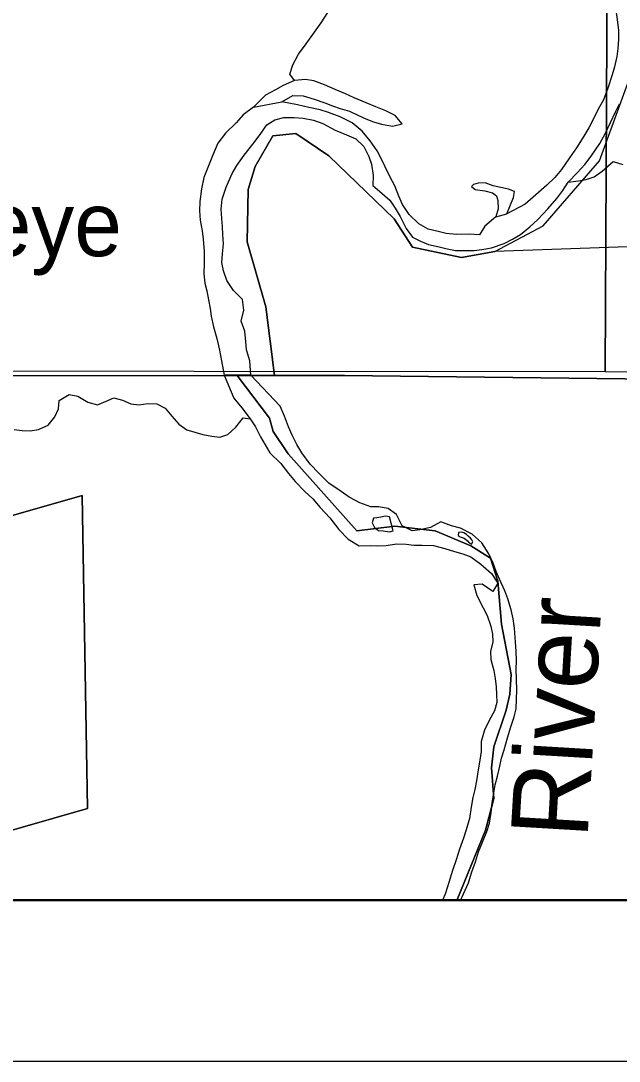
# Model space of a CAD drawing. Extents: x 0 to 680, y 0 to 440.
# Drawn here: x 388.24 to 401.22, y 173.86 to 196.42 of the extents above; entities that cross this region are included whole.
import ezdxf

# ---------------------------------------------------------------- set-up
doc = ezdxf.new("R2010")
doc.units = 0
for name, color, linetype in [('GM_X_Adjacent_County', 7, 'Continuous'), ('GM_X_Corporation', 7, 'Continuous'), ('GM_X_County', 7, 'Continuous'), ('GM_X_Major_River', 7, 'Continuous'), ('GM_X_Major_River_Text', 7, 'Continuous'), ('GM_X_Minor_River', 7, 'Continuous'), ('GM_X_Section', 7, 'Continuous'), ('GM_X_Township', 7, 'Continuous'), ('GM_X_Unincorporated_Text', 7, 'Continuous'), ('SH_Data', 7, 'Continuous'), ('SH_Text', 7, 'Continuous')]:
    doc.layers.add(name, color=color, linetype=linetype)

msp = doc.modelspace()

# ---------------------------------------------------------------- linework, layer by layer
at = {"layer": 'GM_X_Adjacent_County'}
for points in [[(345.039, 415.359), (345.039, 188.757), (345.473, 188.756), (347.217, 188.747), (347.794, 188.745), (350.054, 188.756), (350.975, 188.76), (352.892, 188.767), (353.65, 188.774), (356.075, 188.765), (356.617, 188.773), (363.409, 188.772), (363.555, 188.769), (365.255, 188.724), (373.709, 188.721), (379.321, 188.719), (384.35, 188.722), (392.938, 188.728), (395.267, 188.729), (408.033, 188.58)], [(408.033, 188.58), (395.267, 188.729), (392.938, 188.728), (384.35, 188.722), (379.321, 188.719), (373.709, 188.721), (365.255, 188.724), (363.555, 188.769), (363.409, 188.772), (356.617, 188.773), (356.075, 188.765), (353.65, 188.774), (352.892, 188.767), (350.975, 188.76), (350.054, 188.756), (347.794, 188.745), (347.217, 188.747), (345.473, 188.756), (345.039, 188.757), (345.039, 177.346), (520.893, 177.346)]]:
    msp.add_lwpolyline(points, dxfattribs=at)
at = {"layer": 'GM_X_Corporation'}
for points in [[(387.677, 177.346), (397.702, 177.346), (398.321, 178.866), (398.507, 179.557), (398.454, 180.222), (398.507, 180.675), (398.773, 181.472), (398.853, 181.818), (398.88, 182.244), (398.667, 183.334), (398.587, 184.266), (398.428, 184.771), (398.002, 185.037), (397.231, 185.357), (396.353, 185.463), (395.529, 185.357), (394.04, 187.033), (393.721, 187.512), (393.641, 187.805), (392.94, 188.728), (393.745, 188.728), (393.562, 190.219), (393.157, 191.631), (393.177, 192.766), (393.328, 193.261), (393.712, 193.925), (394.21, 193.978), (394.924, 193.496), (396.34, 192.128), (396.739, 191.515), (397.803, 191.289), (398.528, 191.42), (399.57, 191.974), (400.796, 193.385), (401.458, 195.204)], [(387.677, 177.346), (397.702, 177.346), (398.321, 178.866), (398.507, 179.557), (398.454, 180.222), (398.507, 180.675), (398.773, 181.472), (398.853, 181.818), (398.88, 182.244), (398.667, 183.334), (398.587, 184.266), (398.428, 184.771), (398.002, 185.037), (397.231, 185.357), (396.353, 185.463), (395.529, 185.357), (394.04, 187.033), (393.721, 187.512), (393.641, 187.805), (392.94, 188.728), (393.745, 188.728), (393.562, 190.219), (393.157, 191.631), (393.177, 192.766), (393.328, 193.261), (393.712, 193.925), (394.21, 193.978), (394.924, 193.496), (396.34, 192.128), (396.739, 191.515), (397.803, 191.289), (398.528, 191.42), (399.57, 191.974), (400.796, 193.385), (401.458, 195.204)], [(403.05, 191.578), (398.528, 191.42), (397.803, 191.289), (396.739, 191.515), (396.34, 192.128), (394.924, 193.496), (394.21, 193.978), (393.712, 193.925), (393.328, 193.261), (393.177, 192.766), (393.157, 191.631), (393.562, 190.219), (393.745, 188.728), (392.94, 188.728), (393.641, 187.805), (393.721, 187.512), (394.04, 187.033), (395.529, 185.357), (396.353, 185.463), (397.231, 185.357), (398.002, 185.037), (398.428, 184.771), (398.587, 184.266), (398.667, 183.334), (398.88, 182.244), (398.853, 181.818), (398.773, 181.472), (398.507, 180.675), (398.454, 180.222), (398.507, 179.557), (398.321, 178.866), (397.702, 177.346), (409.232, 177.346)], [(403.05, 191.578), (398.528, 191.42), (397.803, 191.289), (396.739, 191.515), (396.34, 192.128), (394.924, 193.496), (394.21, 193.978), (393.712, 193.925), (393.328, 193.261), (393.177, 192.766), (393.157, 191.631), (393.562, 190.219), (393.745, 188.728), (392.94, 188.728), (393.641, 187.805), (393.721, 187.512), (394.04, 187.033), (395.529, 185.357), (396.353, 185.463), (397.231, 185.357), (398.002, 185.037), (398.428, 184.771), (398.587, 184.266), (398.667, 183.334), (398.88, 182.244), (398.853, 181.818), (398.773, 181.472), (398.507, 180.675), (398.454, 180.222), (398.507, 179.557), (398.321, 178.866), (397.702, 177.346), (409.232, 177.346)], [(385.376, 184.927), (389.574, 186.13), (389.692, 179.338), (387.542, 178.722)], [(385.376, 184.927), (389.574, 186.13), (389.692, 179.338), (387.542, 178.722)]]:
    msp.add_lwpolyline(points, dxfattribs=at)
msp.add_lwpolyline([(372.374, 177.346), (387.677, 177.346), (387.542, 178.722), (389.692, 179.338), (389.574, 186.13), (385.376, 184.927), (385.199, 185.413), (382.81, 184.4), (376.636, 184.293), (376.715, 179.713), (372.374, 180.017)], close=True, dxfattribs=at)
msp.add_lwpolyline([(372.374, 177.346), (387.677, 177.346), (387.542, 178.722), (389.692, 179.338), (389.574, 186.13), (385.376, 184.927), (385.199, 185.413), (382.81, 184.4), (376.636, 184.293), (376.715, 179.713), (372.374, 180.017)], close=True, dxfattribs=at)
at = {"layer": 'GM_X_County'}
for points in [[(345.039, 415.359), (345.039, 188.757), (345.473, 188.756), (347.217, 188.747), (347.794, 188.745), (350.054, 188.756), (350.975, 188.76), (352.892, 188.767), (353.65, 188.774), (356.075, 188.765), (356.617, 188.773), (363.409, 188.772), (363.555, 188.769), (365.255, 188.724), (373.709, 188.721), (379.321, 188.719), (384.35, 188.722), (392.938, 188.728), (395.267, 188.729), (408.033, 188.58)], [(408.033, 188.58), (395.267, 188.729), (392.938, 188.728), (384.35, 188.722), (379.321, 188.719), (373.709, 188.721), (365.255, 188.724), (363.555, 188.769), (363.409, 188.772), (356.617, 188.773), (356.075, 188.765), (353.65, 188.774), (352.892, 188.767), (350.975, 188.76), (350.054, 188.756), (347.794, 188.745), (347.217, 188.747), (345.473, 188.756), (345.039, 188.757), (345.039, 177.346), (520.893, 177.346)]]:
    msp.add_lwpolyline(points, dxfattribs=at)
at = {"layer": 'GM_X_Major_River'}
for p, q in [((393.293, 194.547), (393.908, 194.665)), ((398.548, 192.167), (398.789, 192.238)), ((393.232, 188.734), (392.657, 188.734)), ((392.657, 188.734), (393.232, 188.734))]:
    msp.add_line(p, q, dxfattribs=at)
for points in [[(401.149, 196.658), (401.186, 196.389), (401.21, 196.214), (401.207, 196.013), (401.191, 195.819), (401.168, 195.645), (401.118, 195.424), (401.068, 195.25), (400.977, 194.957), (400.88, 194.71), (400.769, 194.503), (400.679, 194.323), (400.562, 194.097), (400.452, 193.917), (400.294, 193.665), (400.143, 193.446), (399.972, 193.193), (399.828, 193.021), (399.652, 192.856), (399.414, 192.644), (399.183, 192.446), (398.789, 192.238)], [(393.908, 194.665), (394.142, 194.804), (394.37, 194.794), (394.604, 194.723), (394.838, 194.64), (395.005, 194.577), (395.172, 194.521), (395.372, 194.458), (395.552, 194.375), (395.726, 194.292), (395.892, 194.229), (396.066, 194.18), (396.307, 194.136), (396.516, 194.187), (396.364, 194.37), (396.158, 194.467), (395.944, 194.557), (395.731, 194.641), (395.477, 194.751), (395.284, 194.835), (395.064, 194.932), (394.83, 195.035), (394.596, 195.119), (394.416, 195.149), (394.18, 195.125), (393.937, 195.021), (393.768, 194.923), (393.552, 194.805), (393.293, 194.547)], [(393.293, 194.547), (393.069, 194.383), (392.912, 194.21), (392.687, 193.985), (392.517, 193.767), (392.399, 193.493), (392.301, 193.24), (392.217, 193.02), (392.16, 192.779), (392.129, 192.504), (392.12, 192.303), (392.137, 192.095), (392.174, 191.867), (392.198, 191.685), (392.221, 191.417), (392.218, 191.175), (392.214, 190.934), (392.238, 190.732), (392.276, 190.564), (392.314, 190.369), (392.351, 190.181), (392.376, 190.013), (392.426, 189.784), (392.496, 189.535), (392.553, 189.28), (392.597, 189.044), (392.657, 188.734)], [(393.232, 188.734), (393.214, 189.049), (393.137, 189.285), (393.126, 189.466), (393.103, 189.694), (393.025, 189.91), (393.082, 190.144), (393.052, 190.379), (392.86, 190.569), (392.709, 190.786), (392.638, 191.002), (392.607, 191.177), (392.616, 191.364), (392.64, 191.585), (392.629, 191.787), (392.618, 191.961), (392.601, 192.136), (392.59, 192.337), (392.613, 192.551), (392.698, 192.812), (392.829, 193.112), (392.932, 193.285), (393.09, 193.51), (393.275, 193.743), (393.432, 193.955), (393.583, 194.168), (393.752, 194.272), (393.947, 194.323), (394.176, 194.327), (394.37, 194.311), (394.591, 194.267), (394.798, 194.191), (395.064, 194.053), (395.305, 193.949), (395.511, 193.859), (395.683, 193.696), (395.794, 193.479), (395.852, 193.311), (395.883, 193.069), (395.879, 192.848), (396.078, 192.677), (396.251, 192.534), (396.362, 192.358), (396.474, 192.175), (396.604, 191.919), (396.743, 191.729), (396.916, 191.639), (397.089, 191.57), (397.317, 191.52), (397.491, 191.477), (397.671, 191.441), (397.846, 191.439), (398.074, 191.442), (398.242, 191.46), (398.451, 191.497), (398.727, 191.594), (398.91, 191.685), (399.079, 191.79), (399.283, 191.955), (399.46, 192.114), (399.678, 192.345), (399.869, 192.564), (399.999, 192.743), (400.116, 192.923), (400.32, 193.135), (400.477, 193.307), (400.614, 193.486), (400.805, 193.758), (400.923, 193.985), (401.034, 194.218), (401.144, 194.444), (401.227, 194.624)], [(398.548, 192.167), (398.31, 191.969), (398.193, 191.783), (397.965, 191.792), (397.697, 191.79), (397.469, 191.806), (397.295, 191.849), (397.081, 191.899), (396.874, 192.016), (396.669, 192.22), (396.525, 192.436), (396.44, 192.619), (396.356, 192.841), (396.258, 193.03), (396.147, 193.253), (396.069, 193.422), (395.971, 193.598), (395.82, 193.821), (395.648, 194.025), (395.429, 194.209), (395.169, 194.34), (394.915, 194.431), (394.735, 194.487), (394.488, 194.544), (394.247, 194.601), (393.908, 194.665)], [(398.789, 192.238), (398.93, 192.591), (398.952, 192.718), (398.818, 192.773), (398.49, 192.845), (398.317, 192.908), (398.162, 192.903), (398.061, 192.871), (398.02, 192.825), (398.1, 192.763), (398.307, 192.733), (398.475, 192.691), (398.561, 192.629), (398.593, 192.521), (398.597, 192.34), (398.548, 192.167)], [(392.657, 188.734), (392.867, 188.236), (393.037, 188.031), (393.22, 187.786), (393.331, 187.616), (393.441, 187.399), (393.544, 187.223), (393.648, 187.053), (393.885, 186.82), (394.049, 186.602), (394.193, 186.432), (394.403, 186.213), (394.575, 186.055), (394.739, 185.864), (394.949, 185.639), (395.145, 185.387), (395.342, 185.181), (395.581, 185.036), (395.823, 185.044), (395.991, 185.034), (396.165, 185.044), (396.394, 185.08), (396.602, 185.069), (396.77, 185.046), (396.951, 185.049), (397.193, 185.044), (397.44, 184.979), (397.653, 184.914), (397.833, 184.864), (398.007, 184.8), (398.225, 184.635), (398.456, 184.435), (398.593, 184.225), (398.481, 184.046), (398.25, 184.205), (398.068, 184.188), (398.137, 183.959), (398.273, 183.694), (398.357, 183.525), (398.439, 183.295), (398.476, 183.12), (398.479, 182.953), (398.428, 182.746), (398.438, 182.571), (398.5, 182.335), (398.53, 182.16), (398.554, 181.978), (398.564, 181.811), (398.567, 181.636), (398.516, 181.456), (398.404, 181.244), (398.3, 181.038), (398.227, 180.791), (398.23, 180.576), (398.199, 180.389), (398.161, 180.175), (398.13, 179.941), (398.092, 179.754), (398.048, 179.58), (398.011, 179.367), (397.979, 179.119), (397.907, 178.879), (397.842, 178.692), (397.757, 178.459), (397.685, 178.226), (397.607, 177.993), (397.528, 177.733), (397.456, 177.5), (397.387, 177.346)], [(397.782, 177.346), (397.845, 177.485), (397.957, 177.724), (398.029, 177.964), (398.107, 178.184), (398.172, 178.398), (398.257, 178.611), (398.349, 178.843), (398.406, 179.017), (398.445, 179.251), (398.469, 179.458), (398.493, 179.632), (398.531, 179.853), (398.581, 180.039), (398.633, 180.26), (398.67, 180.427), (398.727, 180.613), (398.8, 180.873), (398.872, 181.107), (398.943, 181.327), (398.987, 181.5), (398.998, 181.708), (399.002, 181.909), (398.993, 182.137), (398.991, 182.359), (398.995, 182.54), (398.985, 182.748), (398.976, 182.949), (398.949, 183.252), (398.926, 183.453), (398.883, 183.649), (398.807, 183.885), (398.744, 184.061), (398.628, 184.311), (398.551, 184.481), (398.487, 184.656), (398.397, 184.859), (398.241, 185.097), (398.03, 185.289), (397.777, 185.415), (397.584, 185.466), (397.351, 185.558), (397.133, 185.434), (396.897, 185.385), (396.729, 185.362), (396.516, 185.467), (396.394, 185.711), (396.215, 185.848), (396.001, 185.879), (395.833, 185.883), (395.6, 185.968), (395.368, 186.093), (395.189, 186.211), (394.924, 186.397), (394.707, 186.61), (394.523, 186.808), (394.34, 187.053), (394.229, 187.236), (394.126, 187.433), (394.049, 187.616), (393.96, 187.845), (393.87, 188.062), (393.232, 188.734)], [(396.32, 185.363), (396.238, 185.667), (396.151, 185.675), (396.05, 185.657), (395.963, 185.645), (395.895, 185.633), (395.867, 185.533), (395.918, 185.432)], [(395.918, 185.432), (396.004, 185.37), (396.105, 185.361), (396.238, 185.338), (396.32, 185.363)], [(397.809, 185.334), (397.735, 185.322), (397.727, 185.262), (397.774, 185.227), (397.86, 185.199)], [(397.86, 185.199), (397.887, 185.178), (397.933, 185.143), (397.966, 185.103), (398.019, 185.068), (398.047, 185.121), (398.027, 185.162), (397.995, 185.203), (397.949, 185.244), (397.909, 185.278), (397.856, 185.319), (397.809, 185.334)]]:
    msp.add_lwpolyline(points, dxfattribs=at)
at = {"layer": 'GM_X_Minor_River'}
for points in [[(394.18, 195.125), (394.082, 195.261), (394.145, 195.468), (394.269, 195.701), (394.433, 195.92), (394.612, 196.172), (394.755, 196.378), (394.9, 196.604)], [(400.116, 192.923), (400.338, 192.953), (400.506, 192.978), (400.681, 193.036), (400.851, 193.161), (401.095, 193.372), (401.302, 193.302)], [(388.102, 187.559), (388.276, 187.534), (388.45, 187.53), (388.626, 187.559), (388.836, 187.654), (388.982, 187.832), (389.06, 188.004), (389.078, 188.185), (389.296, 188.314), (389.483, 188.282), (389.695, 188.149), (389.908, 188.09), (390.078, 188.166), (390.261, 188.242), (390.448, 188.197), (390.627, 188.112), (390.814, 188.094), (390.996, 188.123), (391.191, 188.118), (391.376, 188.02), (391.52, 187.848), (391.67, 187.67), (391.848, 187.551), (392.194, 187.449), (392.388, 187.41), (392.562, 187.392), (392.731, 187.449), (392.91, 187.605), (393.069, 187.809), (393.22, 187.786)]]:
    msp.add_lwpolyline(points, dxfattribs=at)
at = {"layer": 'GM_X_Section'}
for points in [[(401.002, 206.368), (418.587, 206.469), (418.28, 188.572), (400.916, 188.809)], [(383.187, 206.393), (401.002, 206.368), (400.916, 188.809), (383.08, 188.821)]]:
    msp.add_lwpolyline(points, close=True, dxfattribs=at)
at = {"layer": 'GM_X_Township'}
for points in [[(345.039, 295.02), (345.039, 188.757), (345.473, 188.756), (347.217, 188.747), (347.794, 188.745), (350.054, 188.756), (350.975, 188.76), (352.892, 188.767), (353.65, 188.774), (356.075, 188.765), (356.617, 188.773), (363.409, 188.772), (363.555, 188.769), (365.255, 188.724), (373.709, 188.721), (379.321, 188.719), (384.35, 188.722), (392.938, 188.728), (395.267, 188.729), (408.033, 188.58), (418.103, 188.464), (418.29, 277.524)], [(408.033, 188.58), (395.267, 188.729), (392.938, 188.728), (393.641, 187.805), (393.721, 187.512), (394.04, 187.033), (395.529, 185.357), (396.353, 185.463), (397.231, 185.357), (398.002, 185.037), (398.428, 184.771), (398.587, 184.266), (398.667, 183.334), (398.88, 182.244), (398.853, 181.818), (398.773, 181.472), (398.507, 180.675), (398.454, 180.222), (398.507, 179.557), (398.415, 179.215), (398.321, 178.866), (397.702, 177.346), (520.893, 177.346)]]:
    msp.add_lwpolyline(points, dxfattribs=at)
at = {"layer": 'SH_Data'}
for p, q in [((345.039, 177.359), (583.039, 177.359)), ((341.539, 173.859), (586.539, 173.859))]:
    msp.add_line(p, q, dxfattribs=at)
at = {"layer": 'SH_Text'}
for points in [[(345.039, 415.359), (583.039, 415.359), (583.039, 177.359), (345.039, 177.359)], [(345.039, 415.359), (345.039, 177.359), (583.038, 177.359), (583.038, 415.359)]]:
    msp.add_lwpolyline(points, close=True, dxfattribs=at)

# ---------------------------------------------------------------- texts
at = {"layer": 'GM_X_Major_River_Text'}
msp.add_text('River', height=1.669, rotation=86.5962, dxfattribs=at).set_placement((400.534, 178.67))
at = {"layer": 'GM_X_Unincorporated_Text'}
msp.add_text('Pigeye', height=1.3919, rotation=0, dxfattribs=at).set_placement((384.747, 191.317))

doc.saveas('drawing.dxf')
